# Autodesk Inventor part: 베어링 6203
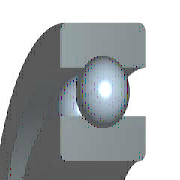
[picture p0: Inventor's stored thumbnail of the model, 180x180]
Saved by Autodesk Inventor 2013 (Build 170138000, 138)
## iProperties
IsCustomPart: 0
Created: 2014-10
Part Number: 베어링 6203
Material: 강철, 연강
Description: 깊은 그루브 볼 베어링
Document SubType Name: Modeling
Standard: KS B 2023
Designer: KYOUNG IL JANG
Standards Organization: KS
Language: ko-KR
Size Designation: 6203 - 17 x 40 x 12
Categories: <MemberInstance><Categories><Category DisplayName="샤프트 부품" InternalName="7f7aeb1f-a693-4053-b835-cee3144e0d98" Mnemonic="SHFT"><Category DisplayName="베어링" Inter
Density: 2.71 g/cm^3
Mass: 22.4044 g
Surface Area: 64.3582 cm^2
Volume: 8.26729 cm^3
Author: SeoGD™ [www.esajin.kr]
Revision Number: 1
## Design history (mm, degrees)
sketch "스케치" dims "d0" = 5.98 (= -0.26 x WD + 0.26 x BD)
  geometry: L1 (3.01, 14.25)-(8.99, 14.25); L2 (6, 14.25)-(6, 11.26); L3 (6, 14.25)-(6, 17.24); L4 (3.778, 12.249)-(0, 12.249); L5 (0, 8.5)-(12, 8.5); L6 (3.778, 16.251)-(0, 16.251); L7 (0, 20)-(12, 20); L8 (12, 8.5)-(12, 12.249); L9 (8.222, 12.249)-(12, 12.249); L10 (8.222, 16.251)-(12, 16.251); L11 (12, 20)-(12, 16.251); L12 (-1.4, 0)-(8.4, 0) reference; L13 (0, -0.3)-(0, 5.3) reference
  constraints: 22 end point, 4 point on line, 2 collinear, 2 perpendicular, 2 symmetric about line, 1 midpoint, 1 parallel, 14 other
  dimensions: "d9" = 17 diameter of L5 L12 (= WD); "d11" = 40 diameter of L7 L12 (= BD); "d12" = 12 distance between parallel lines of L8 L13 (= KB); "d13" = 24.498 diameter of L9 L12 (= 0.326 x BD + 0.674 x WD)
revolve "본체" stored, may be unused: angle "d6" = 90 deg
revolve "볼" stored, may be unused: angle "d7" = 90 deg
pattern_circular "IDS_ARRAYBALL[SIMPL:T]" dims angle "d3" = 360 deg
body "Solid1"
fillet "모깎기1" dims "d1" = 0.6 (= KRS)
other parameters: "WD" = 17 [user parameter; used in 5 equation terms], "BD" = 40 [user parameter; used in 5 equation terms], "KB" = 12 [user parameter; used in 1 equation term], "KRS" = 0.6 [user parameter; used in 1 equation term], "d4" = 0, "d5" = 0, "d8" = 0, "d14" = 0, "d15" = 0, "BBA" = 0 [user parameter], "BC0" = 4750000 [user parameter], "BC" = 9560000 [user parameter], "WR" = 8.5 (= 0.5 x WD) [user parameter]
